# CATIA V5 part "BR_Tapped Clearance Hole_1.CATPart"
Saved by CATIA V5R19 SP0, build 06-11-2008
Bounding box of the stored display mesh (mm): x 19.761 to 31.481, y -55.046 to -43.046, z -40 to 0
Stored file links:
  C:\Program Files\Dassault Systemes\Power Feature\SampleData\SharedData\BusinessRules\BR_RulesPart\BR_Tapped Clearance Hole_1.CATPart
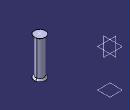
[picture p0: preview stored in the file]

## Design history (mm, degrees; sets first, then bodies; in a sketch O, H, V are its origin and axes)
Set1
  Point1: type OnPlane, Support xy-plane, Direction (1, 0, 0), H 25.621, V -49.046
  Plane1: type Offset, Offset 40, RefPlane xy-plane, reversed
Body1 (main body)
  UdfFeature1 "Tapped Clearance Hole": UdfInputSpec1 AxisSystem1, UdfInputSpec2 Project1, UdfInputSpec3 Intersect1, DG 10, TG 30, DK 8.5, LK 40 {= Body2.Offset + (Sketch1.length(L9) * (Body2.Offset / Body2.Offset ))}, DF1 12, W1 90, DF2 12, W2 90, SR "RH", P 1.5, AS_H 0, AS_D 0, StandardType "No Standard", InternalVersion 1, Through true, Threaded true, UIHidden_zDK 4.25 {= Body2.DK / 2}, UIHidden_zDF1 6 {= Body2.DF1 / 2}, UIHidden_zDF2 6 {= Body2.DF2 / 2}
Body2 "UDF_Body"
  AxisSystem1 "MainAxisSystem": origin (25.621, -49.046, 0), X (-0.7542, -0.6566, 0), Y (0.6566, -0.7542, 0), Z (0, 0, 1)
  Project1 "Project": Support Plane1, ToProject vertex [YZ plane of AxisSystem1 | ZX plane of AxisSystem1 | XY plane of AxisSystem1]
  Intersect1 "Intersect": ToIntersect1 edge [ZX plane of AxisSystem1 | YZ plane of AxisSystem1], ToIntersect2 Plane1
  Sketch1 "MainProfileSketch" on ZX plane of AxisSystem1, origin (25.621, -49.046, 0), H (0.7542, 0.6566, 0), V (0, 0, 1)
    axis line L1 (0, 0) -> (0, -40)
    point P2 (4.25, -38.25)
    line L2 (4.25, -38.25) -> (4.25, -1.75)
    line L3 (4.25, -1.75) -> (6, 0)
    point P3 (6, 0)
    line L4 (6, 0) -> (6, 0)
    line L5 (6, 0) -> (6, 0)
    line L6 (6, 0) -> (0, 0)
    construction line L7 (6, 0) -> (0, 0)
    reference projected line E1 through (0, 0) direction (-1, 0) from edge [XY plane of AxisSystem1 | ZX plane of AxisSystem1]
    reference projected line E2 through (0, 0) direction (-1, 0) from edge [XY plane of AxisSystem1 | ZX plane of AxisSystem1]
    reference projected line E3 through (0, 0) direction (-1, 0) from edge [XY plane of AxisSystem1 | ZX plane of AxisSystem1]
    reference projected line E4 through (0, 0) direction (0, 1) from edge [ZX plane of AxisSystem1 | YZ plane of AxisSystem1]
    line L8 (4.25, -38.25) -> (6, -40)
    point P6 (6, -40)
    line L9 (6, -40) -> (0, -40)
    point P8 (-6, -40)
    point P9 (-4.25, -38.25)
    construction line L10 (-4.25, -38.25) -> (-6, -40)
    point P10 (4.25, -1.75)
    point P11 (-6, 0)
    point P12 (-4.25, -1.75)
    construction line L11 (-4.25, -1.75) -> (-6, 0)
    angle L3 L11 = 90
    "UIHidden_zDK" L1 L2 = 4.25 {= Body2.DK / 2}
    distance E1 L9 = 40 {= Body2.Offset + (Sketch1.length(L9) * (Body2.Offset / Body2.Offset ))}
    length L7 = 6 {= sqrt((Body2.AS_H * Body2.AS_H ) + ((Groove1.top_width / 2 + Groove1.AS_ZR ) * (Groove1.top_width / 2 + Groove1.AS_ZR )))}
    angle L7 L4 = 0 {= atan(Body2.AS_H / (Groove1.top_width / 2 + Groove1.AS_ZR ))}
    angle L8 L10 = 90
    length L9 = 6
    "UIHidden_zDF1" P3 L1 = 6 {= Body2.DF1 / 2}
    "UIHidden_zDF2" P6 L1 = 6 {= Body2.DF2 / 2}
    coincidence: E2 L4, L1 E4
    perpendicularity: L1 L6, E3 L5
    symmetry: P6 P8 L1, P2 P9 L1, L8 L10 L1, P3 P11 L1, P10 P12 L1, L3 L11 L1
  Groove1 "MainGroove": profile Sketch1, axis Sketch1.L1, angle 360
  Thread1 "Tap": diameter 10, depth 30, pitch 1.5, on face of Groove1 from Sketch1.L2, from {plane type Normal, Curve edge [ZX plane of AxisSystem1 | YZ plane of AxisSystem1], RefPoint vertex [YZ plane of AxisSystem1 | ZX plane of AxisSystem1 | XY plane of AxisSystem1]}
  Point2 "LimitingAxisSystemOrigin": type OnCurve, Support edge [ZX plane of AxisSystem1 | YZ plane of AxisSystem1], Length 0 {= (Sketch1.length(L9)) * (Body2.Offset / Body2.Offset)}, RefPoint Intersect1
  AxisSystem2 "LimitingAxisSystem": origin (25.621, -49.046, -40), X (-0.7542, -0.6566, 0), Y (0.6566, -0.7542, 0), Z (0, 0, -1)
Relations
  Body2.W1 = Sketch1.angle(L3 L11)
  Body2.W2 = Sketch1.angle(L8 L10)
  Groove1.top_width = Body2.DF1
  Body2.LK = Sketch1.distance(E1 L9)
  rule "AS_ZR":
    /*Rule created by AKNOPP 03.08.2006*/
    Groove1.AS_ZR = Body2.AS_D - (2 * Sketch1.UIHidden_zDF1(P3 L1))
    if (Body2.AS_D == 0mm)
    {
    	Groove1.AS_ZR = 0mm
    }
    else
    {
    	Groove1.AS_ZR = (Body2.AS_D / 2) - Sketch1.UIHidden_zDF1(P3 L1)
    }
  Body2.DG = Thread1.DG
  Body2.TG = Thread1.TG
  Body2.GB = Thread1.GB
  Body2.P = Thread1.P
